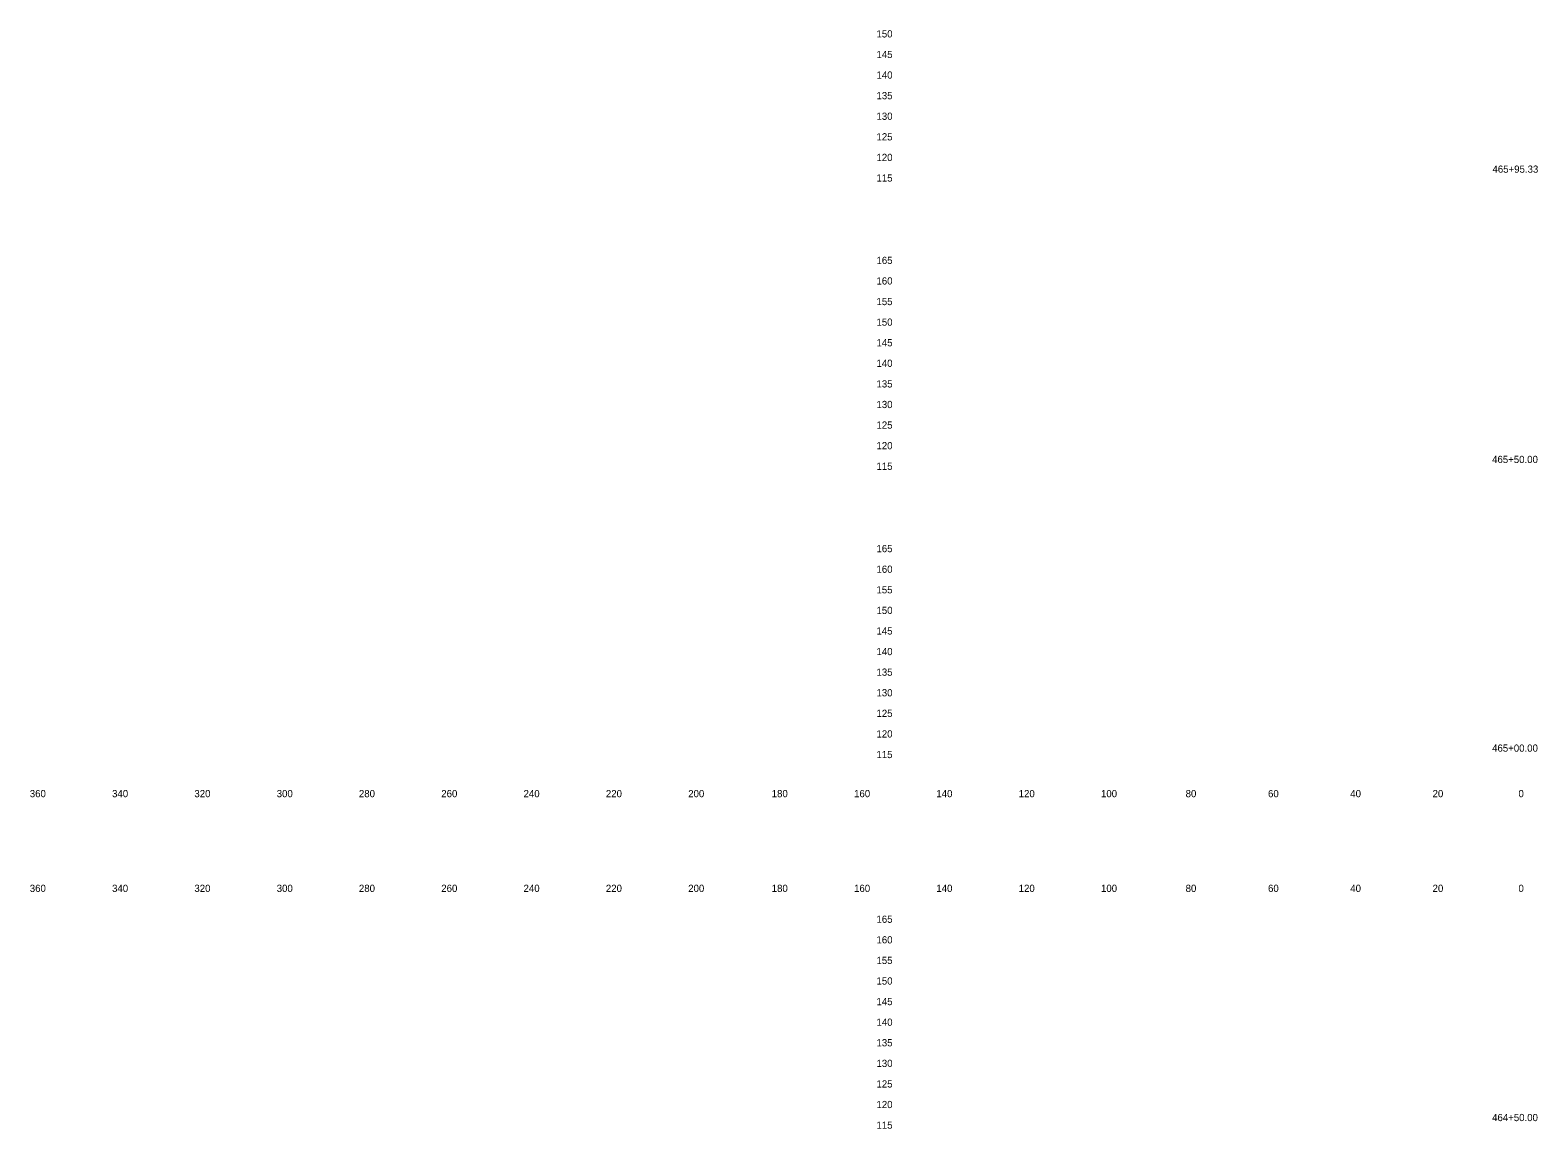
# Model space of a CAD drawing. Extents: x 21281 to 22024, y 6472 to 15198.
# Drawn here: x 21280.5 to 21646.8, y 8924.8 to 9191.6 of the extents above; entities that cross this region are included whole.
import ezdxf

# ---------------------------------------------------------------- set-up
doc = ezdxf.new("R2010")
doc.units = 0
for name, color, linetype in [('Draft_XS_Grid', 7, 'Continuous'), ('Draft_XS_Text', 7, 'Continuous'), ('SLOPE_STAKES_FILL', 7, 'Continuous')]:
    doc.layers.add(name, color=color, linetype=linetype)

msp = doc.modelspace()

# ---------------------------------------------------------------- texts
at = {"layer": 'Draft_XS_Grid'}
for s, p in [('  150  ', (21484.84, 9189.84)), ('  145  ', (21484.84, 9184.84)), ('  140  ', (21484.84, 9179.84)), ('  135  ', (21484.84, 9174.84)), ('  130  ', (21484.84, 9169.84)), ('  125  ', (21484.84, 9164.84)), ('  120  ', (21484.84, 9159.84)), ('  115  ', (21484.84, 9154.84)), ('  165  ', (21484.84, 9134.84)), ('  160  ', (21484.84, 9129.84)), ('  155  ', (21484.84, 9124.84)), ('  150  ', (21484.84, 9119.84)), ('  145  ', (21484.84, 9114.84)), ('  140  ', (21484.84, 9109.84)), ('  135  ', (21484.84, 9104.84)), ('  130  ', (21484.84, 9099.84)), ('  125  ', (21484.84, 9094.84)), ('  120  ', (21484.84, 9089.84)), ('  115  ', (21484.84, 9084.84)), ('  165  ', (21484.84, 9064.84)), ('  160  ', (21484.84, 9059.84)), ('  155  ', (21484.84, 9054.84)), ('  150  ', (21484.84, 9049.84)), ('  145  ', (21484.84, 9044.84)), ('  140  ', (21484.84, 9039.84)), ('  135  ', (21484.84, 9034.84)), ('  130  ', (21484.84, 9029.84)), ('  125  ', (21484.84, 9024.84)), ('  120  ', (21484.84, 9019.84)), ('  115  ', (21484.84, 9014.84)), ('  165  ', (21484.84, 8974.84)), ('  160  ', (21484.84, 8969.84)), ('  155  ', (21484.84, 8964.84)), ('  150  ', (21484.84, 8959.84)), ('  145  ', (21484.84, 8954.84)), ('  140  ', (21484.84, 8949.84)), ('  135  ', (21484.84, 8944.84)), ('  130  ', (21484.84, 8939.84)), ('  125  ', (21484.84, 8934.84)), ('  120  ', (21484.84, 8929.84)), ('  115  ', (21484.84, 8924.84))]:
    msp.add_text(s, height=1.75, dxfattribs=at).set_placement(p)
at = {"layer": 'Draft_XS_Text'}
for s, p in [('  360  ', (21279.14, 9005.34)), ('  340  ', (21299.13, 9005.34)), ('  320  ', (21319.13, 9005.34)), ('  300  ', (21339.13, 9005.34)), ('  280  ', (21359.1, 9005.34)), ('  260  ', (21379.11, 9005.34)), ('  240  ', (21399.1, 9005.34)), ('  220  ', (21419.1, 9005.34)), ('  200  ', (21439.1, 9005.34)), ('  180  ', (21459.39, 9005.34)), ('  160  ', (21479.4, 9005.34)), ('  140  ', (21499.39, 9005.34)), ('  120  ', (21519.39, 9005.34)), ('  100  ', (21539.39, 9005.34)), ('  80  ', (21559.95, 9005.34)), ('  60  ', (21579.97, 9005.34)), ('  40  ', (21599.95, 9005.34)), ('  20  ', (21619.95, 9005.34)), ('  0  ', (21640.81, 9005.34)), ('  0  ', (21640.81, 9005.34)), ('  360  ', (21279.14, 8982.34)), ('  340  ', (21299.13, 8982.34)), ('  320  ', (21319.13, 8982.34)), ('  300  ', (21339.13, 8982.34)), ('  280  ', (21359.1, 8982.34)), ('  260  ', (21379.11, 8982.34)), ('  240  ', (21399.1, 8982.34)), ('  220  ', (21419.1, 8982.34)), ('  200  ', (21439.1, 8982.34)), ('  180  ', (21459.39, 8982.34)), ('  160  ', (21479.4, 8982.34)), ('  140  ', (21499.39, 8982.34)), ('  120  ', (21519.39, 8982.34)), ('  100  ', (21539.39, 8982.34)), ('  80  ', (21559.95, 8982.34)), ('  60  ', (21579.97, 8982.34)), ('  40  ', (21599.95, 8982.34)), ('  20  ', (21619.95, 8982.34)), ('  0  ', (21640.81, 8982.34)), ('  0  ', (21640.81, 8982.34))]:
    msp.add_text(s, height=1.75, dxfattribs=at).set_placement(p)
at = {"layer": 'SLOPE_STAKES_FILL'}
for s, p in [('  465+95.33  ', (21634.5, 9156.99)), ('  465+50.00  ', (21634.41, 9086.5)), ('  465+00.00  ', (21634.41, 9016.4)), ('  464+50.00  ', (21634.41, 8926.68))]:
    msp.add_text(s, height=1.75, dxfattribs=at).set_placement(p)

doc.saveas('drawing.dxf')
